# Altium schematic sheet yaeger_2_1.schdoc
size 127 x 101 mm
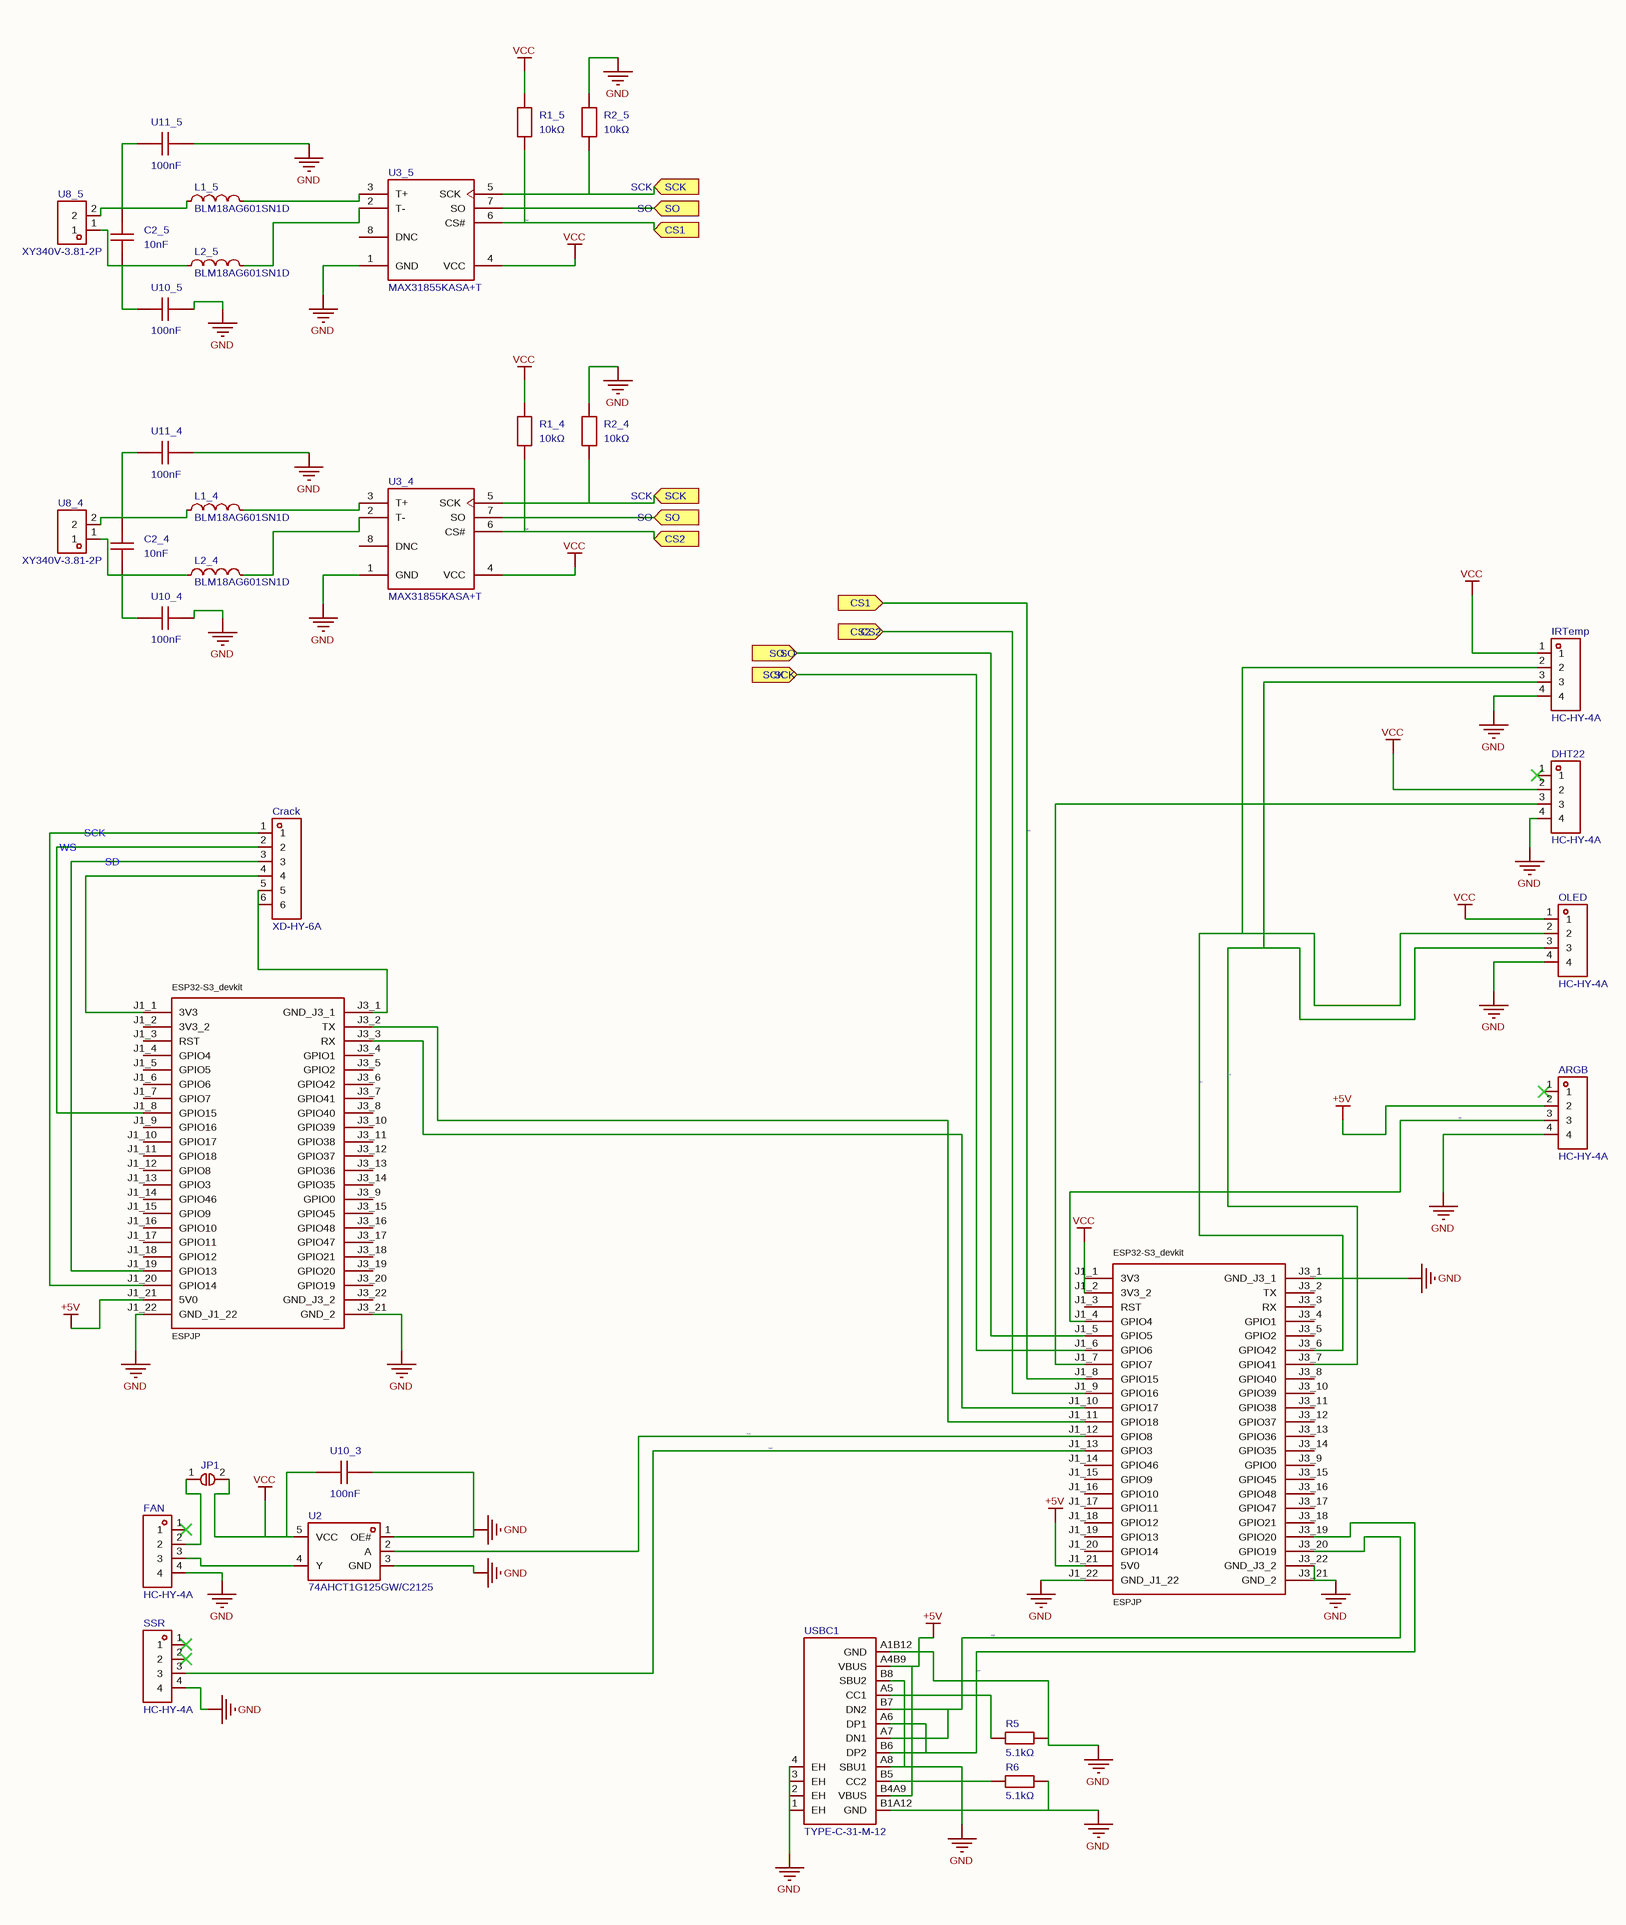
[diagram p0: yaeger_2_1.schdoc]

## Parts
ARGB  HC-HY-4A  [CONN-TH_4P-P2.00_HCTL_HC-HY-4A]
C2_4  10nF  [C0603]
C2_5  10nF  [C0603]
Crack  XD-HY-6A  [CONN-TH_6P-P2.00_HCTL_HC-HY-6A]
DHT22  HC-HY-4A  [CONN-TH_4P-P2.00_HCTL_HC-HY-4A]
FAN  HC-HY-4A  [CONN-TH_4P-P2.00_HCTL_HC-HY-4A]
IRTemp  HC-HY-4A  [CONN-TH_4P-P2.00_HCTL_HC-HY-4A]
JP1  Jumper_SolderJumper_2_Open  [Jumper:SolderJumper-2_P1.3mm_Open_RoundedPad1.0x1.5mm]  (value not drawn)
L1_4  BLM18AG601SN1D  [L0603]
L1_5  BLM18AG601SN1D  [L0603]
L2_4  BLM18AG601SN1D  [L0603]
L2_5  BLM18AG601SN1D  [L0603]
OLED  HC-HY-4A  [CONN-TH_4P-P2.00_HCTL_HC-HY-4A]
R1_4  10kΩ  [R0603]
R1_5  10kΩ  [R0603]
R2_4  10kΩ  [R0603]
R2_5  10kΩ  [R0603]
R5  5.1kΩ  [R0603]
R6  5.1kΩ  [R0603]
SSR  HC-HY-4A  [CONN-TH_4P-P2.00_HCTL_HC-HY-4A]
U1  ESP32-S3-DEVKITM-1-N8  [MODULE_ESP32-S3-DEVKITM-1-N8]  (value not drawn)
U2  74AHCT1G125GW/C2125  [TSSOP-5_L2.1-W1.3-P0.65-LS2.2-BR]
U3_4  MAX31855KASA+T  [SO-8_L4.9-W3.9-P1.27-LS5.9-BL]
U3_5  MAX31855KASA+T  [SO-8_L4.9-W3.9-P1.27-LS5.9-BL]
U6  ESP32-S3-DEVKITM-1-N8  [MODULE_ESP32-S3-DEVKITM-1-N8]  (value not drawn)
U8_4  XY340V-3.81-2P  [CONN-TH_XY340V-3.81-2P]
U8_5  XY340V-3.81-2P  [CONN-TH_XY340V-3.81-2P]
U10_3  100nF  [C0603]
U10_4  100nF  [C0603]
U10_5  100nF  [C0603]
U11_4  100nF  [C0603]
U11_5  100nF  [C0603]
USBC1  TYPE-C-31-M-12  [USB-C_SMD-TYPE-C-31-M-12_1]

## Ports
CS1 (in), CS2 (in), SCK (in), SO (in)

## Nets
+5V: ARGB.2 U1.J1_21(5V0) U6.J1_21(5V0) USBC1.A4B9(VBUS) USBC1.B4A9(VBUS)
GND: ARGB.4 DHT22.4 FAN.4 IRTemp.4 OLED.4 R2_4.2 R2_5.2 R5.2 R6.2 SSR.4 U1.J1_22(GND_J1_22) U1.J3_1(GND_J3_1) U1.J3_21(GND_2) U1.J3_22(GND_J3_2) U2.1(OE#) U2.3(GND) U3_4.1(GND) U3_5.1(GND) U6.J1_22(GND_J1_22) U6.J3_21(GND_2) U10_3.2 U10_4.2 U10_5.2 U11_4.2 U11_5.2 USBC1.1(EH) USBC1.2(EH) USBC1.3(EH) USBC1.4(EH) USBC1.A1B12(GND) USBC1.A8(SBU1) USBC1.B1A12(GND) USBC1.B8(SBU2)
VCC: DHT22.2 IRTemp.1 JP1.2(B) OLED.1 R1_4.2 R1_5.2 U1.J1_1(3V3) U1.J1_2(3V3_2) U2.5(VCC) U3_4.4(VCC) U3_5.4(VCC) U10_3.1
CS2: R1_4.1 R1_5.1 U1.J1_8(GPIO15) U1.J1_9(GPIO16) U3_4.6(CS#) U3_5.6(CS#) ; port CS2, port CS1  [also labelled N$2]
DA: IRTemp.3 OLED.3 U1.J3_7(GPIO41)
FAN: U1.J1_12(GPIO8) U2.2(A)
N$1: ARGB.3 U1.J1_4(GPIO4)
N$4: U1.J3_20(GPIO19) USBC1.A7(DN1) USBC1.B7(DN2)
N$7: U1.J3_19(GPIO20) USBC1.A6(DP1) USBC1.B6(DP2)
SC: IRTemp.2 OLED.2 U1.J3_6(GPIO42)
SCK: R2_4.1 R2_5.1 U1.J1_6(GPIO6) U3_4.5(SCK) U3_5.5(SCK) ; port SCK
SO: U1.J1_5(GPIO5) U3_4.7(SO) U3_5.7(SO) ; port SO
SSR: SSR.3 U1.J1_13(GPIO3)
NetC2_4_1: C2_4.1 L2_4.1 U8_4.1 U10_4.1
NetC2_4_2: C2_4.2 L1_4.1 U8_4.2 U11_4.1
NetC2_5_1: C2_5.1 L2_5.1 U8_5.1 U10_5.1
NetC2_5_2: C2_5.2 L1_5.1 U8_5.2 U11_5.1
NetCrack_1: Crack.1 U6.J1_20(GPIO14)
NetCrack_2: Crack.2 U6.J1_8(GPIO15)
NetCrack_3: Crack.3 U6.J1_19(GPIO13)
NetCrack_4: Crack.4 U6.J1_1(3V3)
NetCrack_5: Crack.5 Crack.6 U6.J3_1(GND_J3_1)
NetDHT22_3: DHT22.3 U1.J1_7(GPIO7)
NetFAN_2: FAN.2 JP1.1(A)
NetFAN_3: FAN.3 U2.4(Y)
NetL1_4_2: L1_4.2 U3_4.3(T+)
NetL1_5_2: L1_5.2 U3_5.3(T+)
NetL2_4_2: L2_4.2 U3_4.2(T-)
NetL2_5_2: L2_5.2 U3_5.2(T-)
NetR5_1: R5.1 USBC1.A5(CC1)
NetR6_1: R6.1 USBC1.B5(CC2)
NetU1_J1_10: U1.J1_10(GPIO17) U6.J3_3(RX)
NetU1_J1_11: U1.J1_11(GPIO18) U6.J3_2(TX)

Not connected (* = marked no-connect by the designer): ARGB 1*; DHT22 1*; FAN 1*; SSR 1* 2*; U1 J1_3(RST) J1_14(GPIO46) J1_15(GPIO9) J1_16(GPIO10) J1_17(GPIO11) J1_18(GPIO12) J1_19(GPIO13) J1_20(GPIO14) J3_2(TX) J3_3(RX) J3_4(GPIO1) J3_5(GPIO2) J3_8(GPIO40) J3_9(GPIO0) J3_10(GPIO39) J3_11(GPIO38) J3_12(GPIO37) J3_13(GPIO36) J3_14(GPIO35) J3_15(GPIO45) J3_16(GPIO48) J3_17(GPIO47) J3_18(GPIO21); U3_4 8(DNC); U3_5 8(DNC); U6 J1_2(3V3_2) J1_3(RST) J1_4(GPIO4) J1_5(GPIO5) J1_6(GPIO6) J1_7(GPIO7) J1_9(GPIO16) J1_10(GPIO17) J1_11(GPIO18) J1_12(GPIO8) J1_13(GPIO3) J1_14(GPIO46) J1_15(GPIO9) J1_16(GPIO10) J1_17(GPIO11) J1_18(GPIO12) J3_4(GPIO1) J3_5(GPIO2) J3_6(GPIO42) J3_7(GPIO41) J3_8(GPIO40) J3_9(GPIO0) J3_10(GPIO39) J3_11(GPIO38) J3_12(GPIO37) J3_13(GPIO36) J3_14(GPIO35) J3_15(GPIO45) J3_16(GPIO48) J3_17(GPIO47) J3_18(GPIO21) J3_19(GPIO20) J3_20(GPIO19) J3_22(GND_J3_2)

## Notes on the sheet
- Labels drawn without touching a wire or pin: SCK, SD, WS

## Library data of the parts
ARGB DHT22 OLED = HC-HY-4A: Pins Structure:1x4P Pitch:2mm Mounting Style:Direct Insert Reference Series:HY Number of Pins:4P Number of Rows:1 Number of PINs Per Row:4 Row Spacing:- Current Rating (Max):2A Contact Material:Brass Contact Plating:Tin Operating Temperature Range:-25℃~+8; Manufacturer: HCTL(华灿天禄); AddInBom: yes; ModelId: f44454f43a6b4f0dbbbf1e3fec5677df0819f05c4eef4c71ace90d822a990e87; ModelTransform: 393.7,200.787,0,180,0,0,0,-15.748,-118.11; Pins Structure: 1x4P; Pitch: 2mm; Reference Series: HY; Number of PINs Per Row: 4; Current Rating (Max): 2A; Rated Voltage (Max): 250V; Plastic Material: PA66; Z-Height of the Board: 7.8mm; X-Length of Bottom Edge on Board (Spacing Line): 10mm; Y-Width of Bottom Edge on Board: 5.1mm
C2_4 = C0603X103K025T: Capacitance:10nF Tolerance:±10% Tolerance:±10% Voltage Rating:25V Temperature Coefficient:-; Manufacturer: IHHEC(禾伸堂); Reuse Block: max; Group ID: 3; Channel ID: $1I248; 3D Model: 624118aa3cc7497086c383c2d72e08520819f05c4eef4c71ace90d822a990e87; 3D Model Transform: 62.992,31.496,0,0,0,0,0,0,0; Tolerance: ±10%; Voltage Rating: 25V; AddInBom: yes; ModelName: C0603_L1.6-W0.8-H0.8
C2_5 = C0603X103K025T: Capacitance:10nF Tolerance:±10% Tolerance:±10% Voltage Rating:25V Temperature Coefficient:-; Manufacturer: IHHEC(禾伸堂); Reuse Block: max; Group ID: 4; Channel ID: $1I248; 3D Model: 624118aa3cc7497086c383c2d72e08520819f05c4eef4c71ace90d822a990e87; 3D Model Transform: 62.992,31.496,0,0,0,0,0,0,0; Tolerance: ±10%; Voltage Rating: 25V; AddInBom: yes; ModelName: C0603_L1.6-W0.8-H0.8
Crack = XD-HY-6A: Pins Structure:1x6P Pitch:2mm Mounting Type:Through Hole Number of Pins:6P Number of Rows:1 Number of PINs Per Row:6 Current Rating:2A Operating Temperature:-25℃~+85℃ Operating Temperature:-25℃~+85℃ Voltage Rating:250V Plastic Material:PA66 Flame Retardan; Manufacturer: XUNDA(讯答); AddInBom: yes; ModelId: 346497cf354a4fb383f93bc6b2064f990819f05c4eef4c71ace90d822a990e87; ModelTransform: 551.18,200.787,0,0,0,0,0,16.142,-118.11; Pins Structure: 1x6P; Pitch: 2mm; Number of PINs Per Row: 6; Current Rating: 2A; Voltage Rating: 250V; Plastic Material: PA66; Flame Retardant Rating: UL94V-0; Z-Height of the Board: 7.8mm; X-Length of Bottom Edge on Board (Spacing Line): 13.5mm; Y-Width of Bottom Edge on Board: 6.2mm
FAN IRTemp SSR = HC-HY-4A: Pins Structure:1x4P Pitch:2mm Mounting Style:Direct Insert Reference Series:HY Number of Pins:4P Number of Rows:1 Number of PINs Per Row:4 Row Spacing:- Current Rating (Max):2A Contact Material:Brass Contact Plating:Tin Operating Temperature Range:-25℃~+8; Manufacturer: HCTL(华灿天禄); 3D Model: f44454f43a6b4f0dbbbf1e3fec5677df0819f05c4eef4c71ace90d822a990e87; 3D Model Transform: 393.7,200.787,0,180,0,0,0,-15.748,-118.11; Pins Structure: 1x4P; Pitch: 2mm; Reference Series: HY; Number of PINs Per Row: 4; Current Rating (Max): 2A; Rated Voltage (Max): 250V; Plastic Material: PA66; Z-Height of the Board: 7.8mm; X-Length of Bottom Edge on Board (Spacing Line): 10mm; Y-Width of Bottom Edge on Board: 5.1mm; AddInBom: yes
JP1 = Jumper_SolderJumper_2_Open: AddInBom: yes
L1_4 = BLM18AG601SN1D: Impedance @ Frequency:600Ω@100MHz Tolerance:±25% Tolerance:±25% DC Resistance(DCR):380mΩ Current Rating:500mA Number of Circuits:1 Operating Temperature:-55℃~+125℃ Operating Temperature:-55℃~+125℃; Manufacturer: muRata(村田); Reuse Block: max; Group ID: 3; Channel ID: $1I265; 3D Model: ece81e7160a84e0c9a4133ba5d41d18a0819f05c4eef4c71ace90d822a990e87; 3D Model Transform: 62.992,31.496,0,180,0,0,0.094,0.629,0; Tolerance: ±25%; DC Resistance(DCR): 380mΩ; Current Rating: 500mA; Number of Circuits: 1; AddInBom: yes; ModelName: L0603_L1.6-W0.8-H0.5_BEAD
L1_5 = BLM18AG601SN1D: Impedance @ Frequency:600Ω@100MHz Tolerance:±25% Tolerance:±25% DC Resistance(DCR):380mΩ Current Rating:500mA Number of Circuits:1 Operating Temperature:-55℃~+125℃ Operating Temperature:-55℃~+125℃; Manufacturer: muRata(村田); Reuse Block: max; Group ID: 4; Channel ID: $1I265; 3D Model: ece81e7160a84e0c9a4133ba5d41d18a0819f05c4eef4c71ace90d822a990e87; 3D Model Transform: 62.992,31.496,0,180,0,0,0.094,0.629,0; Tolerance: ±25%; DC Resistance(DCR): 380mΩ; Current Rating: 500mA; Number of Circuits: 1; AddInBom: yes; ModelName: L0603_L1.6-W0.8-H0.5_BEAD
L2_4 = BLM18AG601SN1D: Impedance @ Frequency:600Ω@100MHz Tolerance:±25% Tolerance:±25% DC Resistance(DCR):380mΩ Current Rating:500mA Number of Circuits:1 Operating Temperature:-55℃~+125℃ Operating Temperature:-55℃~+125℃; Manufacturer: muRata(村田); Reuse Block: max; Group ID: 3; Channel ID: $1I266; 3D Model: ece81e7160a84e0c9a4133ba5d41d18a0819f05c4eef4c71ace90d822a990e87; 3D Model Transform: 62.992,31.496,0,180,0,0,0.094,0.629,0; Tolerance: ±25%; DC Resistance(DCR): 380mΩ; Current Rating: 500mA; Number of Circuits: 1; AddInBom: yes; ModelName: L0603_L1.6-W0.8-H0.5_BEAD
L2_5 = BLM18AG601SN1D: Impedance @ Frequency:600Ω@100MHz Tolerance:±25% Tolerance:±25% DC Resistance(DCR):380mΩ Current Rating:500mA Number of Circuits:1 Operating Temperature:-55℃~+125℃ Operating Temperature:-55℃~+125℃; Manufacturer: muRata(村田); Reuse Block: max; Group ID: 4; Channel ID: $1I266; 3D Model: ece81e7160a84e0c9a4133ba5d41d18a0819f05c4eef4c71ace90d822a990e87; 3D Model Transform: 62.992,31.496,0,180,0,0,0.094,0.629,0; Tolerance: ±25%; DC Resistance(DCR): 380mΩ; Current Rating: 500mA; Number of Circuits: 1; AddInBom: yes; ModelName: L0603_L1.6-W0.8-H0.5_BEAD
R1_4 = SCR0603J10K: Type:Thick Film Resistors Resistance: Tolerance:±5% Tolerance:±5% Power(Watts): Overload Voltage (Max): Operating Temperature Range:-55℃~+155℃ Operating Temperature Range:-55℃~+155℃; Manufacturer: VO(翔胜); Group ID: 3; Channel ID: $1I257; 3D Model: 112863783b5b41f1b5254f87eedc79320819f05c4eef4c71ace90d822a990e87; 3D Model Transform: 31.8897,63.7794,0,90,0,0,0,0,0; Tolerance: ±5%; AddInBom: yes
R1_5 = SCR0603J10K: Type:Thick Film Resistors Resistance: Tolerance:±5% Tolerance:±5% Power(Watts): Overload Voltage (Max): Operating Temperature Range:-55℃~+155℃ Operating Temperature Range:-55℃~+155℃; Manufacturer: VO(翔胜); Group ID: 4; Channel ID: $1I257; 3D Model: 112863783b5b41f1b5254f87eedc79320819f05c4eef4c71ace90d822a990e87; 3D Model Transform: 31.8897,63.7794,0,90,0,0,0,0,0; Tolerance: ±5%; AddInBom: yes
R2_4 = SCR0603J10K: Type:Thick Film Resistors Resistance: Tolerance:±5% Tolerance:±5% Power(Watts): Overload Voltage (Max): Operating Temperature Range:-55℃~+155℃ Operating Temperature Range:-55℃~+155℃; Manufacturer: VO(翔胜); Group ID: 3; Channel ID: $1I258; 3D Model: 112863783b5b41f1b5254f87eedc79320819f05c4eef4c71ace90d822a990e87; 3D Model Transform: 31.8897,63.7794,0,90,0,0,0,0,0; Tolerance: ±5%; AddInBom: yes
R2_5 = SCR0603J10K: Type:Thick Film Resistors Resistance: Tolerance:±5% Tolerance:±5% Power(Watts): Overload Voltage (Max): Operating Temperature Range:-55℃~+155℃ Operating Temperature Range:-55℃~+155℃; Manufacturer: VO(翔胜); Group ID: 4; Channel ID: $1I258; 3D Model: 112863783b5b41f1b5254f87eedc79320819f05c4eef4c71ace90d822a990e87; 3D Model Transform: 31.8897,63.7794,0,90,0,0,0,0,0; Tolerance: ±5%; AddInBom: yes
R5 R6 = 0603WAF5101T5E: Type:Thick Film Resistor Resistance:5.1kΩ Tolerance:±1% Tolerance:±1% Power(Watts):100mW Voltage-Supply(Max):75V Temperature Coefficient:±100ppm/℃ Temperature Coefficient:±100ppm/℃ Operating Temperature:-55℃~+155℃ Operating Temperature:-55℃~+155℃; Manufacturer: UNI-ROYAL(厚声); AddInBom: yes; ModelId: 112863783b5b41f1b5254f87eedc79320819f05c4eef4c71ace90d822a990e87; ModelTransform: 31.8897,63.7794,0,90,0,0,0,0,0; Tolerance: ±1%; Power(Watts): 100mW; Voltage-Supply(Max): 75V
U1 = ESP32-S3-DEVKITM-1-N8_ESPJP_: UniqueId: 1bdc0ab44f99f92d; MF: Espressif Systems; Package1: None; AddInBom: yes
U2 = 74AHCT1G125GW/C2125: output type:Tri-State Voltage - Supply:4.5V~5.5V Voltage - Supply:4.5V~5.5V Number of Elements:1 Number of Bits per Element:1 Current - Output Low(IOL):8mA Current - Output High(IOH):8mA Logic Family:74AHCT Operating Temperature:-40℃~+125℃ Operating Tempe; Manufacturer: Nexperia(安世); AddInBom: yes; ModelId: f9996f70ec594f1fa1f051d0da75de4b0819f05c4eef4c71ace90d822a990e87; ModelName: TSSOP-5_L2.1-W1.3-H1.1-LS2.2-P0.65; ModelTransform: 82.677,86.614,0,90,0,0,-0.002,0.002,0; Number of Elements: 1; Current - Output Low(IOL): 8mA; Logic Family: 74AHCT; Quiescent Current: 40uA; Propagation Delay: 9.5ns@5.5V,50pF
U3_4 = MAX31855KASA+T: Resolution (Bits):14 Number of Channels:- Voltage - Supply:3V~3.6V Voltage - Supply:3V~3.6V Interface Type:SPI The Chip Type:Thermocouple-to-Digital Converter Operating Temperature:-40℃~+125℃ Operating Temperature:-40℃~+125℃ Sampling Rate:- Quiescent Curr; Manufacturer: ADI(亚德诺)/MAXIM(美信); Reuse Block: max; Group ID: 3; Channel ID: $1I235; 3D Model: 548305ef4d1f4879a4f47128885951540819f05c4eef4c71ace90d822a990e87; 3D Model Transform: 240.39054,192.913,0,270,0,0,0.0005,-0.0005,0; Resolution (Bits): 14; Interface Type: SPI; Quiescent Current (Iq): 1500uA; AddInBom: yes; ModelName: SO-8_L4.9-W3.9-H1.5-LS5.9-P1.27
U3_5 = MAX31855KASA+T: Resolution (Bits):14 Number of Channels:- Voltage - Supply:3V~3.6V Voltage - Supply:3V~3.6V Interface Type:SPI The Chip Type:Thermocouple-to-Digital Converter Operating Temperature:-40℃~+125℃ Operating Temperature:-40℃~+125℃ Sampling Rate:- Quiescent Curr; Manufacturer: ADI(亚德诺)/MAXIM(美信); Reuse Block: max; Group ID: 4; Channel ID: $1I235; 3D Model: 548305ef4d1f4879a4f47128885951540819f05c4eef4c71ace90d822a990e87; 3D Model Transform: 240.39054,192.913,0,270,0,0,0.0005,-0.0005,0; Resolution (Bits): 14; Interface Type: SPI; Quiescent Current (Iq): 1500uA; AddInBom: yes; ModelName: SO-8_L4.9-W3.9-H1.5-LS5.9-P1.27
U6 = ESP32-S3-DEVKITM-1-N8_ESPJP_: MF: Espressif Systems; Package1: None; AddInBom: yes
U8_4 = XY340V-3.81-2P: Number of Positions or Pins:1x2P Pitch:3.81mm Color:Green Mounting Type:Through Hole Number of Pins:2P Number of Rows:1 Number of PINs Per Row:2 Screw Specification:M2 Current Rating:7A Voltage Rating (Max):300V Wire Gauge - AWG:18~24 Wire Gauge - mm2:1 W; Manufacturer: XINLAIYA(新莱亚); Group ID: 3; Channel ID: $1I246; 3D Model: 4ef887ec1e2e4a95b008f9208d1cbdb50819f05c4eef4c71ace90d822a990e87; 3D Model Transform: 331.4954,279.527,0,0,0,0,0,-18.307,-137.795; Number of Positions or Pins: 1x2P; Pitch: 3.81mm; Number of PINs Per Row: 2; Screw Specification: M2; Current Rating: 7A; Voltage Rating (Max): 300V; Wire Gauge - AWG: 18~24; Wire Gauge - mm2: 1; AddInBom: yes
U8_5 = XY340V-3.81-2P: Number of Positions or Pins:1x2P Pitch:3.81mm Color:Green Mounting Type:Through Hole Number of Pins:2P Number of Rows:1 Number of PINs Per Row:2 Screw Specification:M2 Current Rating:7A Voltage Rating (Max):300V Wire Gauge - AWG:18~24 Wire Gauge - mm2:1 W; Manufacturer: XINLAIYA(新莱亚); Group ID: 4; Channel ID: $1I246; 3D Model: 4ef887ec1e2e4a95b008f9208d1cbdb50819f05c4eef4c71ace90d822a990e87; 3D Model Transform: 331.4954,279.527,0,0,0,0,0,-18.307,-137.795; Number of Positions or Pins: 1x2P; Pitch: 3.81mm; Number of PINs Per Row: 2; Screw Specification: M2; Current Rating: 7A; Voltage Rating (Max): 300V; Wire Gauge - AWG: 18~24; Wire Gauge - mm2: 1; AddInBom: yes
U10_3 = 0603Y0160104JDR: Capacitance:100nF Tolerance:±5% Tolerance:±5% Voltage Rating:16V Temperature Coefficient:-; Manufacturer: Knowles(楼氏); Reuse Block: max; Group ID: 2; Channel ID: $1I250; 3D Model: 624118aa3cc7497086c383c2d72e08520819f05c4eef4c71ace90d822a990e87; 3D Model Transform: 62.992,31.496,0,0,0,0,0,0,0; Tolerance: ±5%; Voltage Rating: 16V; AddInBom: yes; ModelName: C0603_L1.6-W0.8-H0.8
U10_4 = 0603Y0160104JDR: Capacitance:100nF Tolerance:±5% Tolerance:±5% Voltage Rating:16V Temperature Coefficient:-; Manufacturer: Knowles(楼氏); Reuse Block: max; Group ID: 3; Channel ID: $1I250; 3D Model: 624118aa3cc7497086c383c2d72e08520819f05c4eef4c71ace90d822a990e87; 3D Model Transform: 62.992,31.496,0,0,0,0,0,0,0; Tolerance: ±5%; Voltage Rating: 16V; AddInBom: yes; ModelName: C0603_L1.6-W0.8-H0.8
U10_5 = 0603Y0160104JDR: Capacitance:100nF Tolerance:±5% Tolerance:±5% Voltage Rating:16V Temperature Coefficient:-; Manufacturer: Knowles(楼氏); Reuse Block: max; Group ID: 4; Channel ID: $1I250; 3D Model: 624118aa3cc7497086c383c2d72e08520819f05c4eef4c71ace90d822a990e87; 3D Model Transform: 62.992,31.496,0,0,0,0,0,0,0; Tolerance: ±5%; Voltage Rating: 16V; AddInBom: yes; ModelName: C0603_L1.6-W0.8-H0.8
U11_4 = 0603Y0160104JDR: Capacitance:100nF Tolerance:±5% Tolerance:±5% Voltage Rating:16V Temperature Coefficient:-; Manufacturer: Knowles(楼氏); Reuse Block: max; Group ID: 3; Channel ID: $1I251; 3D Model: 624118aa3cc7497086c383c2d72e08520819f05c4eef4c71ace90d822a990e87; 3D Model Transform: 62.992,31.496,0,0,0,0,0,0,0; Tolerance: ±5%; Voltage Rating: 16V; AddInBom: yes; ModelName: C0603_L1.6-W0.8-H0.8
U11_5 = 0603Y0160104JDR: Capacitance:100nF Tolerance:±5% Tolerance:±5% Voltage Rating:16V Temperature Coefficient:-; Manufacturer: Knowles(楼氏); Reuse Block: max; Group ID: 4; Channel ID: $1I251; 3D Model: 624118aa3cc7497086c383c2d72e08520819f05c4eef4c71ace90d822a990e87; 3D Model Transform: 62.992,31.496,0,0,0,0,0,0,0; Tolerance: ±5%; Voltage Rating: 16V; AddInBom: yes; ModelName: C0603_L1.6-W0.8-H0.8
USBC1 = TYPE-C-31-M-12: Connector Type:Type-C Protocol Standard:- Gender:Female Mounting Type:Surface Mount, Right Angle Number of Contacts:16P Number of Ports:1 Current Rating-Power:5A Voltage Rating:20V Connect-Disconnect Life:10,000 cycles Length:7.35mm Operating Temperature:; Manufacturer: 韩国韩荣; AddInBom: yes; ModelId: 8421221a464047838322348b3a9debc30819f05c4eef4c71ace90d822a990e87; ModelTransform: 351.9678,311.023,0,180,0,0,0,-43.307,-33.465; Connector Type: Type-C; Gender: Female; Number of Contacts: 16P; Number of Ports: 1; Current Rating-Power: 5A; Voltage Rating: 20V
